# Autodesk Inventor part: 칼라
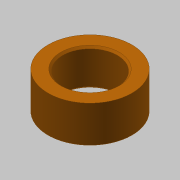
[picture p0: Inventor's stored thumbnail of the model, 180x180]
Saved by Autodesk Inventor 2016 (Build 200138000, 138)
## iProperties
Created: 2015-09
Part Number: 칼라
Document SubType Name: Modeling
Designer: mduedu
Density: 1 g/cm^3
Material: 스테인리스강
Appearance: 주황색
Author: mduedu
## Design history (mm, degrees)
node "작업 평면1"
node "작업 평면2"
sketch "스케치1"
  geometry: C1 r 7.5 at (0, 0); C2 r 11.5 at (0, 0); 1 further point
  constraints: 2 centre point, 2 coincident
  dimensions: "d0" = 15 diameter of C1; "d1" = 23 diameter of C2
extrude "돌출1" new body sketch "스케치1" stored distance "d2" = 9.85; taper "d3" = 0 deg
chamfer "모따기1" distance "d4" = 0.5; stored, may be unused: second distance "d5" = 2, angle "d6" = 45 deg
node "솔리드1"
